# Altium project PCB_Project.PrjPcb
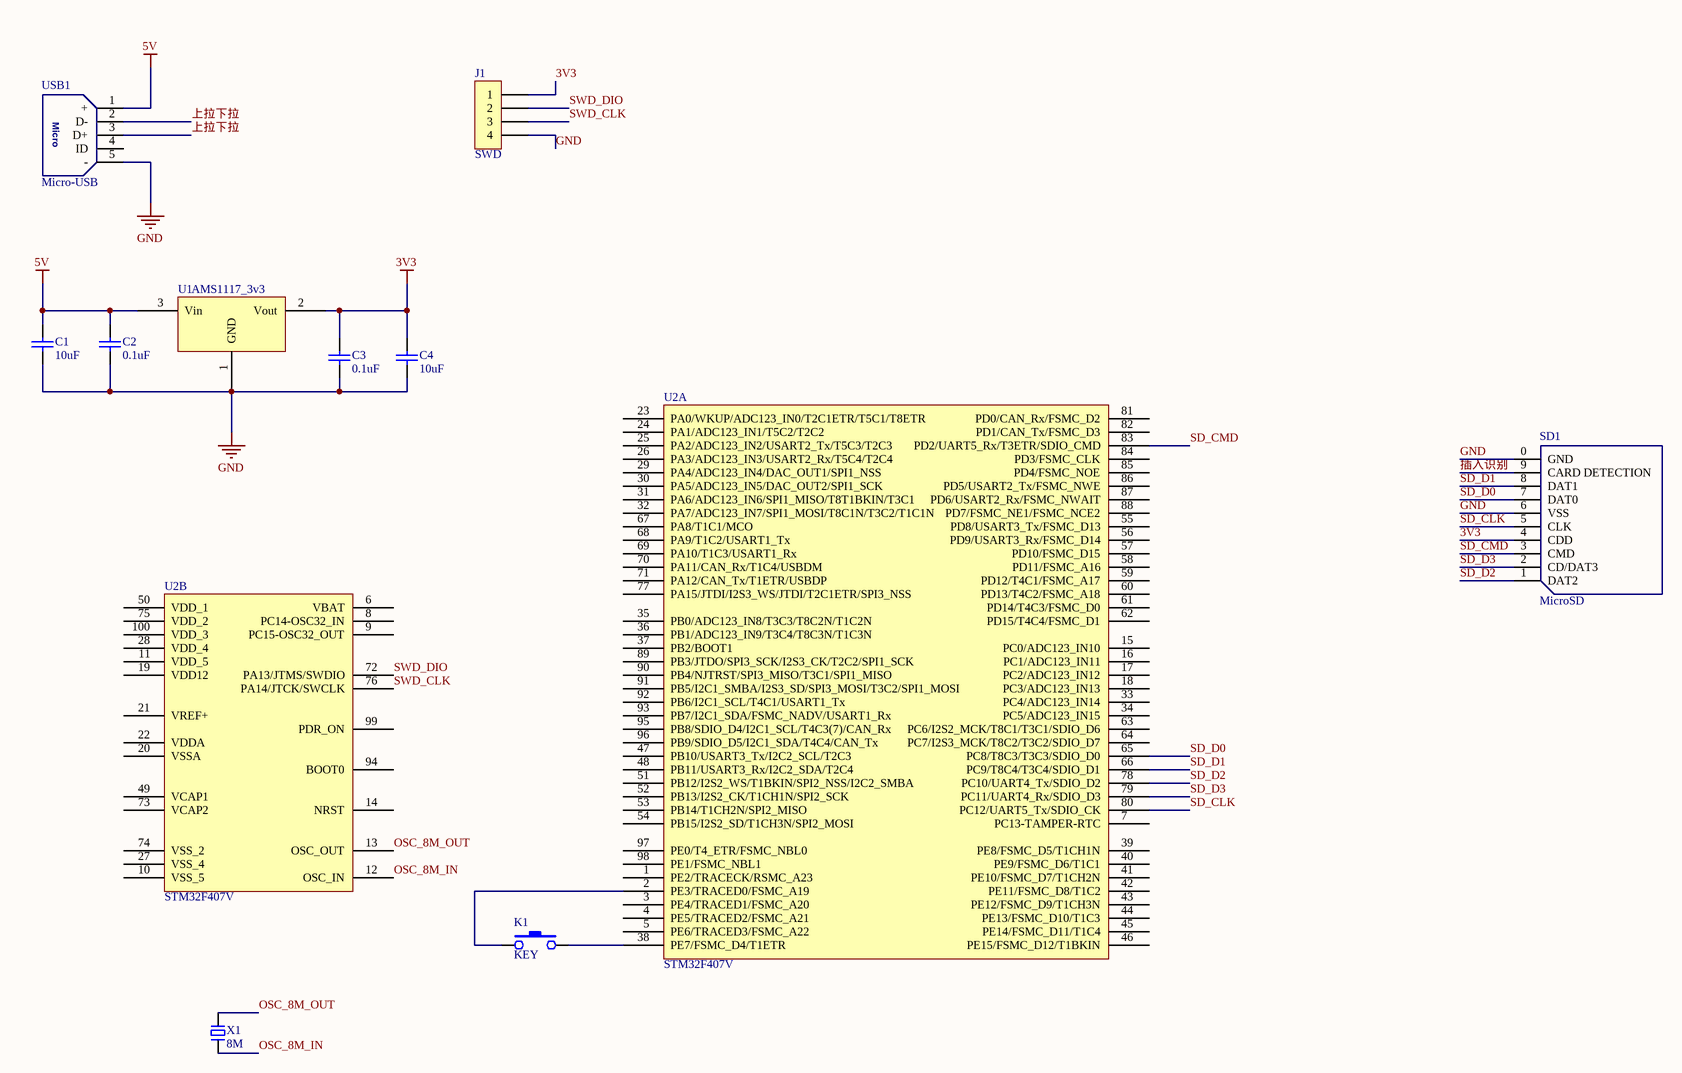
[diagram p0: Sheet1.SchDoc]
1 sheet, 11 parts. Net scope: global (net labels, ports and power ports of the same name join across sheets).
Board file: PCB1.PcbDoc

## Sheet Sheet1.SchDoc
size A3

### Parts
C1  value 10uF  [C-RAD-0603]  (hidden comment: Cap)
C2  value 0.1uF  [C-RAD-0603]  (hidden comment: Cap)
C3  value 0.1uF  [C-RAD-0603]  (hidden comment: Cap)
C4  value 10uF  [C-RAD-0603]  (hidden comment: Cap)
J1  SWD  [Pin HDR1X4/2.54mm-S]
K1  KEY  [DIP-6X6X6]
SD1  MicroSD  [Micro SD]
U1  AMS1117_3v3  [SOT223]
U2  STM32F407V  [LQFP-100_M]  (parts A,B of 2)
USB1  Micro-USB  [USB-MICRO_A]
X1  8M  [OSC HC-49S]

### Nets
3V3: C3.2 C4.2 J1.1 SD1.4(CDD) U1.2(Vout)
5V: C1.2 C2.2 U1.3(Vin) USB1.1(+)
GND: C1.1 C2.1 C3.1 C4.1 J1.4 SD1.0(GND) SD1.6(VSS) U1.1(GND) USB1.5(-)
OSC_8M_IN: U2.12(OSC_IN) X1.1
OSC_8M_OUT: U2.13(OSC_OUT) X1.2
SD_CLK: SD1.5(CLK) U2.80(PC12/UART5_Tx/SDIO_CK)
SD_CMD: SD1.3(CMD) U2.83(PD2/UART5_Rx/T3ETR/SDIO_CMD)
SD_D0: SD1.7(DAT0) U2.65(PC8/T8C3/T3C3/SDIO_D0)
SD_D1: SD1.8(DAT1) U2.66(PC9/T8C4/T3C4/SDIO_D1)
SD_D2: SD1.1(DAT2) U2.78(PC10/UART4_Tx/SDIO_D2)
SD_D3: SD1.2(CD/DAT3) U2.79(PC11/UART4_Rx/SDIO_D3)
SWD_CLK: J1.3 U2.76(PA14/JTCK/SWCLK)
SWD_DIO: J1.2 U2.72(PA13/JTMS/SWDIO)
上拉下拉: USB1.2(D-) USB1.3(D+)
插入识别: SD1.9(CARD_DETECTION)
NetK1_1: K1.1 U2.2(PE3/TRACED0/FSMC_A19)
NetK1_3: K1.3 U2.38(PE7/FSMC_D4/T1ETR)

Not connected (* = marked no-connect by the designer): U2 1(PE2/TRACECK/RSMC_A23) 3(PE4/TRACED1/FSMC_A20) 4(PE5/TRACED2/FSMC_A21) 5(PE6/TRACED3/FSMC_A22) 6(VBAT) 7(PC13-TAMPER-RTC) 8(PC14-OSC32_IN) 9(PC15-OSC32_OUT) 10(VSS_5) 11(VDD_5) 14(NRST) 15(PC0/ADC123_IN10) 16(PC1/ADC123_IN11) 17(PC2/ADC123_IN12) 18(PC3/ADC123_IN13) 19(VDD12) 20(VSSA) 21(VREF+) 22(VDDA) 23(PA0/WKUP/ADC123_IN0/T2C1ETR/T5C1/T8ETR) 24(PA1/ADC123_IN1/T5C2/T2C2) 25(PA2/ADC123_IN2/USART2_Tx/T5C3/T2C3) 26(PA3/ADC123_IN3/USART2_Rx/T5C4/T2C4) 27(VSS_4) 28(VDD_4) 29(PA4/ADC123_IN4/DAC_OUT1/SPI1_NSS) 30(PA5/ADC123_IN5/DAC_OUT2/SPI1_SCK) 31(PA6/ADC123_IN6/SPI1_MISO/T8T1BKIN/T3C1) 32(PA7/ADC123_IN7/SPI1_MOSI/T8C1N/T3C2/T1C1N) 33(PC4/ADC123_IN14) 34(PC5/ADC123_IN15) 35(PB0/ADC123_IN8/T3C3/T8C2N/T1C2N) 36(PB1/ADC123_IN9/T3C4/T8C3N/T1C3N) 37(PB2/BOOT1) 39(PE8/FSMC_D5/T1CH1N) 40(PE9/FSMC_D6/T1C1) 41(PE10/FSMC_D7/T1CH2N) 42(PE11/FSMC_D8/T1C2) 43(PE12/FSMC_D9/T1CH3N) 44(PE13/FSMC_D10/T1C3) 45(PE14/FSMC_D11/T1C4) 46(PE15/FSMC_D12/T1BKIN) 47(PB10/USART3_Tx/I2C2_SCL/T2C3) 48(PB11/USART3_Rx/I2C2_SDA/T2C4) 49(VCAP1) 50(VDD_1) 51(PB12/I2S2_WS/T1BKIN/SPI2_NSS/I2C2_SMBA) 52(PB13/I2S2_CK/T1CH1N/SPI2_SCK) 53(PB14/T1CH2N/SPI2_MISO) 54(PB15/I2S2_SD/T1CH3N/SPI2_MOSI) 55(PD8/USART3_Tx/FSMC_D13) 56(PD9/USART3_Rx/FSMC_D14) 57(PD10/FSMC_D15) 58(PD11/FSMC_A16) 59(PD12/T4C1/FSMC_A17) 60(PD13/T4C2/FSMC_A18) 61(PD14/T4C3/FSMC_D0) 62(PD15/T4C4/FSMC_D1) 63(PC6/I2S2_MCK/T8C1/T3C1/SDIO_D6) 64(PC7/I2S3_MCK/T8C2/T3C2/SDIO_D7) 67(PA8/T1C1/MCO) 68(PA9/T1C2/USART1_Tx) 69(PA10/T1C3/USART1_Rx) 70(PA11/CAN_Rx/T1C4/USBDM) 71(PA12/CAN_Tx/T1ETR/USBDP) 73(VCAP2) 74(VSS_2) 75(VDD_2) 77(PA15/JTDI/I2S3_WS/JTDI/T2C1ETR/SPI3_NSS) 81(PD0/CAN_Rx/FSMC_D2) 82(PD1/CAN_Tx/FSMC_D3) 84(PD3/FSMC_CLK) 85(PD4/FSMC_NOE) 86(PD5/USART2_Tx/FSMC_NWE) 87(PD6/USART2_Rx/FSMC_NWAIT) 88(PD7/FSMC_NE1/FSMC_NCE2) 89(PB3/JTDO/SPI3_SCK/I2S3_CK/T2C2/SPI1_SCK) 90(PB4/NJTRST/SPI3_MISO/T3C1/SPI1_MISO) 91(PB5/I2C1_SMBA/I2S3_SD/SPI3_MOSI/T3C2/SPI1_MOSI) 92(PB6/I2C1_SCL/T4C1/USART1_Tx) 93(PB7/I2C1_SDA/FSMC_NADV/USART1_Rx) 94(BOOT0) 95(PB8/SDIO_D4/I2C1_SCL/T4C3(7)/CAN_Rx) 96(PB9/SDIO_D5/I2C1_SDA/T4C4/CAN_Tx) 97(PE0/T4_ETR/FSMC_NBL0) 98(PE1/FSMC_NBL1) 99(PDR_ON) 100(VDD_3); USB1 4(ID)

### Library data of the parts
C1-C4 = Cap: 无极性电容
J1 = Pin HDR1X4
U1 = AMS1117: 三端稳压芯片
U2 = STM32F407V: STM32单片机100引脚
X1 = XTAL-2P: 2脚无源脚晶振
